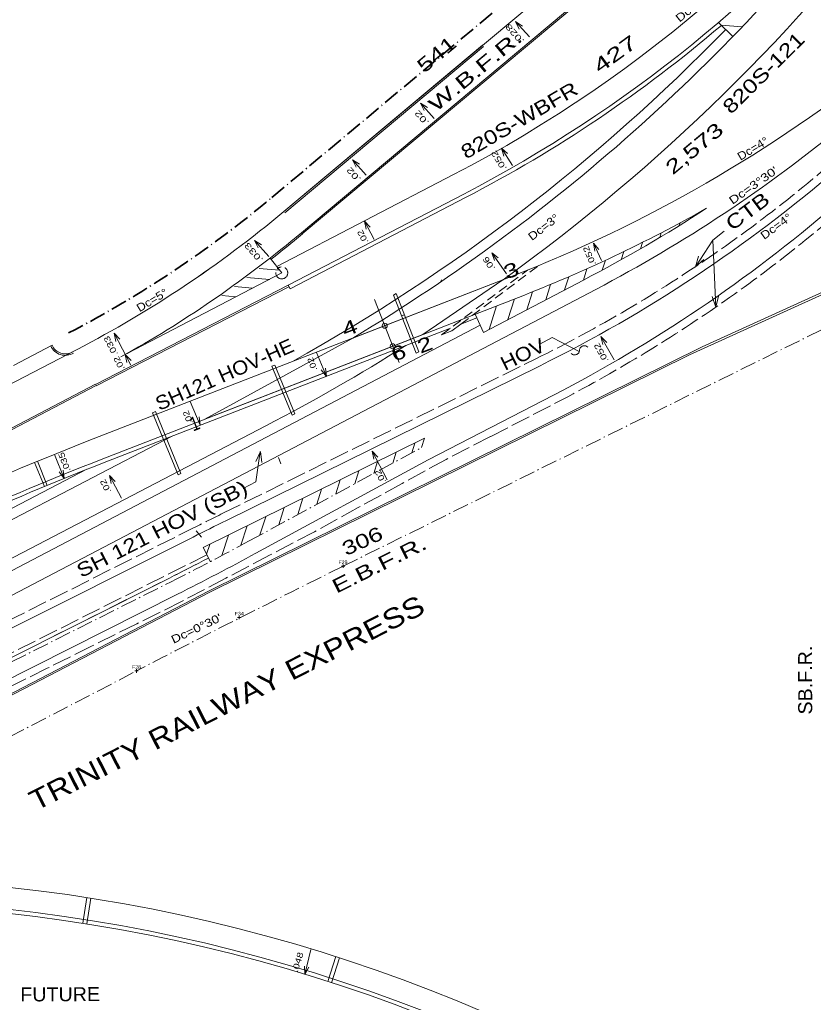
# Model space of a CAD drawing. Extents: x 2354993 to 2372084, y 6966390 to 6990057.
# Drawn here: x 2363431 to 2364225, y 6978118 to 6979100 of the extents above; entities that cross this region are included whole.
import ezdxf
from ezdxf.enums import TextEntityAlignment as Align

# ---------------------------------------------------------------- set-up
doc = ezdxf.new("R2010")
doc.units = 0
doc.header["$LTSCALE"] = 3.2
for name, pattern in [('DOT_DASHED', [7.7, 5, -1.2, 0.3, -1.2]), ('LONG_DASH_SHORT_DASH', [9.9, 6, -1.2, 1.5, -1.2]), ('LONG_DASHED', [7.5, 6, -1.5]), ('MEDIUM_DASHED', [4.5, 3, -1.5])]:
    doc.linetypes.add(name, pattern=pattern)
for name, color, linetype, lineweight in [('13', 7, 'Continuous', 13), ('17', 7, 'Continuous', 13), ('19', 7, 'Continuous', 13), ('23', 7, 'Continuous', 13), ('25', 7, 'Continuous', 13), ('28', 7, 'Continuous', 13), ('4', 7, 'Continuous', 13), ('5', 7, 'Continuous', 13), ('50', 7, 'LONG_DASH_SHORT_DASH', 13), ('6', 7, 'Continuous', 13), ('63', 7, 'Continuous', 13), ('9', 7, 'Continuous', 13)]:
    doc.layers.add(name, color=color, linetype=linetype, lineweight=lineweight)

msp = doc.modelspace()

# ---------------------------------------------------------------- linework, layer by layer
at = {"layer": '13'}
for p, q in [((2364124.311, 6978879.327), (2364135.635, 6978888.419)), ((2364124.311, 6978879.327), (2364107.051, 6978852.9)), ((2364124.311, 6978879.327), (2364127.473, 6978812.622)), ((2364107.051, 6978852.9), (2364110.158, 6978863.536)), ((2364107.051, 6978852.9), (2364115.294, 6978860.305)), ((2364127.472, 6978812.623), (2364123.858, 6978823.097)), ((2364127.473, 6978812.623), (2364129.916, 6978823.431)), ((2363667.59, 6978638.063), (2363671.897, 6978668.354)), ((2363672.046, 6978668.333), (2363667.62, 6978658.174)), ((2363672.047, 6978668.332), (2363673.633, 6978657.367)), ((2363667.59, 6978638.063), (2363654.762, 6978631.255))]:
    msp.add_line(p, q, dxfattribs=at)
for points in [[(2363950.859, 6978775.281), (2363963.619, 6978782.215), (2363990.892, 6978768.256)], [(2363999.577, 6978772.4), (2363998.454, 6978773.318), (2363997.504, 6978773.752), (2363996.636, 6978773.955), (2363995.824, 6978774), (2363995.058, 6978773.917), (2363994.332, 6978773.719), (2363993.644, 6978773.414), (2363992.997, 6978772.994), (2363992.396, 6978772.447), (2363991.85, 6978771.741), (2363991.388, 6978770.804), (2363991.214, 6978770.222), (2363991.098, 6978769.385), (2363990.979, 6978768.546), (2363990.806, 6978767.966), (2363990.674, 6978767.642), (2363990.343, 6978767.028), (2363990.06, 6978766.627), (2363989.798, 6978766.322), (2363989.197, 6978765.776), (2363988.55, 6978765.356), (2363987.863, 6978765.05), (2363987.137, 6978764.854), (2363986.37, 6978764.771), (2363985.559, 6978764.814), (2363984.69, 6978765.018), (2363984.046, 6978765.284), (2363983.739, 6978765.452), (2363983.238, 6978765.793), (2363982.618, 6978766.368)]]:
    msp.add_lwpolyline(points, dxfattribs=at)
at = {"layer": '17'}
for p, q in [((2363268.695, 6978481.439), (2363677.359, 6978693.821)), ((2363498.546, 6978222.377), (2363494.553, 6978196.824)), ((2363502.498, 6978221.759), (2363498.505, 6978196.207)), ((2363747.446, 6978163.351), (2363739.437, 6978138.405)), ((2363751.255, 6978162.128), (2363743.245, 6978137.182))]:
    msp.add_line(p, q, dxfattribs=at)
at = {"layer": '19'}
for p, q in [((2363927.094, 6979097.931), (2363930.771, 6979090.484)), ((2363927.094, 6979097.931), (2363934.149, 6979093.538)), ((2363941.005, 6979082.577), (2363927.094, 6979097.931)), ((2363832.045, 6979016.466), (2363835.722, 6979009.019)), ((2363832.045, 6979016.466), (2363839.1, 6979012.073)), ((2363845.956, 6979001.112), (2363832.045, 6979016.466)), ((2363913.032, 6978971.577), (2363915.358, 6978963.604)), ((2363913.032, 6978971.577), (2363919.215, 6978966.024)), ((2363924.06, 6978954.036), (2363913.032, 6978971.577)), ((2363763.983, 6978959.742), (2363767.66, 6978952.295)), ((2363763.983, 6978959.742), (2363771.038, 6978955.349)), ((2363777.894, 6978944.388), (2363763.983, 6978959.742)), ((2363776.001, 6978898.486), (2363777.835, 6978890.386)), ((2363776.001, 6978898.486), (2363781.833, 6978892.566)), ((2363785.936, 6978880.304), (2363776.001, 6978898.486)), ((2363666.116, 6978879.256), (2363669.793, 6978871.809)), ((2363666.116, 6978879.256), (2363673.171, 6978874.863)), ((2363680.616, 6978863.252), (2363666.116, 6978879.256)), ((2364005.199, 6978876.561), (2364006.371, 6978868.339)), ((2364005.199, 6978876.561), (2364010.533, 6978870.187)), ((2364012.986, 6978859.082), (2364005.199, 6978876.561)), ((2363903.322, 6978866.925), (2363909.75, 6978861.657)), ((2363525.767, 6978786.4), (2363527.497, 6978778.277)), ((2363525.767, 6978786.4), (2363531.523, 6978780.405)), ((2363542.615, 6978754.612), (2363525.767, 6978786.4)), ((2364012.378, 6978783.117), (2364014.392, 6978775.06)), ((2364012.378, 6978783.117), (2364018.341, 6978777.327)), ((2364025.8, 6978759.806), (2364012.378, 6978783.117)), ((2363532.44, 6978762.884), (2363539.021, 6978766.379)), ((2363536.944, 6978765.222), (2363538.674, 6978757.099)), ((2363536.944, 6978765.222), (2363542.7, 6978759.227)), ((2363728.247, 6978767.198), (2363738.051, 6978743.352)), ((2363738.051, 6978743.352), (2363732.905, 6978749.878)), ((2363738.051, 6978743.352), (2363737.118, 6978751.605)), ((2363601.957, 6978718.326), (2363611.761, 6978694.48)), ((2363611.761, 6978694.48), (2363610.828, 6978702.733)), ((2363466.118, 6978665.11), (2363475.922, 6978641.264)), ((2363783.747, 6978668.654), (2363785.477, 6978660.531)), ((2363783.747, 6978668.654), (2363789.503, 6978662.659)), ((2363798.92, 6978640.025), (2363783.747, 6978668.654)), ((2363475.922, 6978641.264), (2363470.776, 6978647.79)), ((2363475.922, 6978641.264), (2363474.989, 6978649.517)), ((2363521.224, 6978644.262), (2363522.954, 6978636.139)), ((2363521.224, 6978644.262), (2363526.98, 6978638.267)), ((2363533.298, 6978621.481), (2363521.224, 6978644.262)), ((2363613.023, 6978582.513), (2363607.877, 6978589.039)), ((2363716.338, 6978145.542), (2363716.086, 6978153.85))]:
    msp.add_line(p, q, dxfattribs=at)
for points in [[(2363918.021, 6978845.743), (2363903.322, 6978866.925), (2363906.006, 6978859.066)], [(2363722.648, 6978170.541), (2363716.338, 6978145.542), (2363720.499, 6978152.731)]]:
    msp.add_lwpolyline(points, dxfattribs=at)
at = {"layer": '23'}
msp.add_line((2363928.757, 6978804.834), (2363928.732, 6978804.883), dxfattribs=at)
at = {"layer": '25'}
for p, q in [((2363695.384, 6978907.983), (2364072.128, 6979223.133)), ((2363911.877, 6979053.229), (2364089.77, 6979202.039)), ((2363912.839, 6979052.078), (2364090.732, 6979200.888)), ((2364130.07, 6979096.947), (2364144.412, 6979083.009)), ((2363695.379, 6978907.981), (2363894.233, 6979074.323)), ((2363696.341, 6978906.829), (2363895.195, 6979073.173)), ((2363713.023, 6978886.887), (2363911.877, 6979053.229)), ((2363713.984, 6978885.737), (2363912.839, 6979052.079)), ((2363699.848, 6978834.335), (2363875.325, 6978925.541)), ((2363693.391, 6978846.757), (2363681.807, 6978861.611)), ((2363538.707, 6978766.357), (2363693.391, 6978846.757)), ((2363507.097, 6978735.295), (2363699.848, 6978834.335)), ((2363507.783, 6978733.961), (2363700.534, 6978833.001)), ((2363701.693, 6978830.785), (2363699.848, 6978834.335)), ((2363038.234, 6978322.559), (2364007.4, 6978830.292)), ((2363512.767, 6978660.249), (2363930.064, 6978822.286)), ((2363886.744, 6978805.465), (2363895.028, 6978787.227)), ((2358006.591, 6975920.846), (2363488.891, 6978770.331)), ((2363638.158, 6978599.34), (2363950.965, 6978753.691)), ((2363833.285, 6978672.206), (2363836.223, 6978681.461)), ((2362811.106, 6978184.667), (2363604.71, 6978582.7)), ((2363622.04, 6978558.072), (2363614.958, 6978572.167)), ((2363756.487, 6978553.588), (2363752.987, 6978553.588)), ((2363756.493, 6978553.591), (2363752.993, 6978553.591)), ((2363754.737, 6978555.338), (2363754.737, 6978551.838)), ((2363754.743, 6978555.341), (2363754.743, 6978551.841)), ((2363143.211, 6978301.576), (2363589.111, 6978525.607)), ((2363652.658, 6978502.288), (2363649.158, 6978502.288)), ((2363652.658, 6978502.288), (2363649.158, 6978502.288)), ((2363650.908, 6978504.038), (2363650.908, 6978500.538)), ((2363650.908, 6978504.038), (2363650.908, 6978500.538)), ((2363548.137, 6978450.65), (2363548.137, 6978447.15)), ((2363548.144, 6978450.653), (2363548.144, 6978447.153)), ((2363549.887, 6978448.9), (2363546.387, 6978448.9)), ((2363549.894, 6978448.903), (2363546.394, 6978448.903))]:
    msp.add_line(p, q, dxfattribs=at)
at = {"layer": '25', "linetype": 'LONG_DASHED'}
for p, q in [((2363634.618, 6978606.514), (2363947.425, 6978760.865)), ((2363902.287, 6978683.113), (2363968.888, 6978717.538)), ((2363902.235, 6978683.214), (2363857.739, 6978660.407)), ((2363857.675, 6978660.373), (2363813.85, 6978636.301)), ((2363813.786, 6978636.267), (2363769.961, 6978612.195)), ((2363769.897, 6978612.161), (2363726.072, 6978588.089)), ((2362775.435, 6978175.726), (2363601.123, 6978589.851)), ((2363726.072, 6978588.089), (2363681.803, 6978564.844)), ((2363618.55, 6978565.019), (2362905.562, 6978206.794)), ((2363681.803, 6978564.844), (2363637.534, 6978541.599)), ((2363135.13, 6978317.66), (2363581.03, 6978541.691)), ((2363637.533, 6978541.601), (2363593.264, 6978518.356)), ((2363593.265, 6978518.356), (2363548.487, 6978496.107)), ((2363548.488, 6978496.107), (2363503.71, 6978473.858)), ((2363503.711, 6978473.858), (2363458.933, 6978451.609)), ((2363458.934, 6978451.609), (2363414.156, 6978429.36))]:
    msp.add_line(p, q, dxfattribs=at)
at = {"layer": '25'}
msp.add_lwpolyline([(2363667.497, 6978566.51), (2363839.951, 6978659.895), (2363965.216, 6978724.645)], dxfattribs=at)
for centre, radius, start, end in [((2363247.127, 6980134.169), 1362.136, 297.46364, 320.4266), ((2362792.03, 6980397.363), 1885.859, 301.04574, 322.89258), ((2363323.326, 6980025.663), 1418.395, 296.26348, 310.78211), ((2363406.512, 6980170.6), 1446.395, 291.22127, 299.46693), ((2363298.192, 6980015.937), 1453.395, 297.31887, 310.6767), ((2362961.103, 6979785.775), 1144.416, 297.46365, 309.91281), ((2362961.101, 6979785.775), 1171.963, 299.53559, 309.91255), ((2362961.101, 6979785.775), 1173.462, 307.94874, 309.91255), ((2364544.669, 6976002.774), 2850.789, 111.22127, 117.46089), ((2366179.689, 6973448.679), 5743.578, 116.26348, 116.63614), ((2362296.691, 6981097.975), 2878.789, 296.67607, 298.43586)]:
    msp.add_arc(centre, radius, start, end, dxfattribs=at)
at = {"layer": '25', "linetype": 'LONG_DASHED'}
for centre, radius, start, end in [((2363323.326, 6980025.663), 1410.395, 296.26348, 313.14638), ((2363298.192, 6980015.937), 1461.395, 297.31887, 312.20163), ((2366179.689, 6973448.679), 5751.578, 116.26348, 116.63614), ((2362296.691, 6981097.975), 2860.789, 296.67607, 297.55731)]:
    msp.add_arc(centre, radius, start, end, dxfattribs=at)
at = {"layer": '28'}
msp.add_line((2363692.6, 6978656.074), (2363690.033, 6978662.131), dxfattribs=at)
at = {"layer": '4'}
for p, q in [((2364132.776, 6979094.317), (2364153.623, 6979092.553)), ((2363688.388, 6978853.171), (2363865.179, 6978945.061)), ((2363701.693, 6978830.785), (2363877.17, 6978921.991)), ((2363658.618, 6978842.121), (2363681.022, 6978840.327)), ((2363670.716, 6978851.185), (2363691.218, 6978849.543)), ((2363646.219, 6978833.081), (2363664.295, 6978831.633)), ((2363633.508, 6978824.067), (2363647.572, 6978822.941))]:
    msp.add_line(p, q, dxfattribs=at)
for centre, radius, start, end in [((2363247.127, 6980134.169), 1340.136, 297.46364, 325.00264), ((2362792.03, 6980397.361), 1919.859, 305.78394, 323.02193), ((2362792.03, 6980397.363), 1875.859, 299.08835, 315.81698), ((2363247.127, 6980134.169), 1366.136, 297.46364, 310.42224), ((2362792.03, 6980397.361), 1919.859, 297.46086, 302.28095)]:
    msp.add_arc(centre, radius, start, end, dxfattribs=at)
at = {"layer": '5'}
for p, q in [((2364091.724, 6978896.81), (2364090.85, 6978894.042)), ((2364072.843, 6978886.833), (2364071.375, 6978882.184)), ((2364054.093, 6978877.273), (2364052.06, 6978870.836)), ((2364035.469, 6978868.114), (2364032.897, 6978859.975)), ((2364016.964, 6978859.339), (2364013.878, 6978849.575)), ((2363504.803, 6978680.758), (2363922.1, 6978842.795)), ((2363980.304, 6978842.888), (2363976.143, 6978829.722)), ((2363998.577, 6978850.935), (2363994.993, 6978839.597)), ((2363852.973, 6978839.977), (2363852.165, 6978837.688)), ((2363895.028, 6978787.227), (2363994.993, 6978839.597)), ((2363962.138, 6978835.184), (2363957.29, 6978819.845)), ((2363255.18, 6978436.214), (2364007.4, 6978830.292)), ((2363944.076, 6978827.812), (2363938.437, 6978809.968)), ((2364101.183, 6978764.916), (2364238.257, 6978827.035)), ((2364113.723, 6978772.795), (2364238.524, 6978829.352)), ((2363908.183, 6978813.789), (2363900.732, 6978790.215)), ((2363926.115, 6978820.752), (2363919.585, 6978800.092)), ((2363244.971, 6978455.701), (2363891.715, 6978794.521)), ((2363872.294, 6978795.563), (2363888.401, 6978801.817)), ((2363514.215, 6978656.52), (2363861.967, 6978791.553)), ((2363425.177, 6978754.243), (2363463.775, 6978774.478)), ((2363482.757, 6978767.142), (2363488.89, 6978770.33)), ((2363620.009, 6978528.496), (2364113.723, 6978772.795)), ((2363620.695, 6978527.162), (2364101.183, 6978764.916)), ((2362654.988, 6978292.473), (2363507.292, 6978735.395)), ((2362655.626, 6978291.114), (2363508.018, 6978734.082)), ((2362391.142, 6978063.692), (2363583.984, 6978683.611)), ((2363614.958, 6978572.167), (2363836.223, 6978681.461)), ((2363826.447, 6978676.637), (2363823.35, 6978666.838)), ((2363807.809, 6978667.441), (2363804.378, 6978656.588)), ((2363789.173, 6978658.245), (2363785.408, 6978646.338)), ((2363248.405, 6978520.48), (2363498.513, 6978650.46)), ((2363770.533, 6978649.048), (2363766.437, 6978636.089)), ((2363751.895, 6978639.85), (2363747.465, 6978625.838)), ((2363733.259, 6978630.655), (2363728.496, 6978615.589)), ((2363714.618, 6978621.457), (2363709.525, 6978605.339)), ((2363695.982, 6978612.261), (2363690.554, 6978595.09)), ((2363677.345, 6978603.064), (2363671.584, 6978584.84)), ((2363658.704, 6978593.866), (2363652.612, 6978574.59)), ((2363640.067, 6978584.67), (2363633.642, 6978564.34)), ((2363621.409, 6978575.408), (2363618.289, 6978565.537)), ((2363135.13, 6978317.66), (2363581.03, 6978541.691)), ((2363620.009, 6978528.496), (2363045.424, 6978230.005)), ((2363620.695, 6978527.162), (2363049.66, 6978230.516))]:
    msp.add_line(p, q, dxfattribs=at)
for centre, radius, start, end in [((2363406.512, 6980170.6), 1424.395, 291.22127, 308.69896), ((2363336.186, 6980111.513), 1446.395, 297.64942, 309.4527), ((2363333.422, 6980115.951), 1437.622, 297.39902, 303.07689), ((2362961.102, 6979785.775), 1144.416, 297.46365, 309.91255), ((2363476.995, 6978780.281), 15.938, 203.70124, 301.18072), ((2363476.995, 6978780.281), 14.438, 203.70124, 301.18072), ((2364544.669, 6976002.774), 2872.789, 111.22127, 117.46089), ((2364544.669, 6976002.774), 2846.789, 111.22127, 117.46089), ((2362296.691, 6981097.975), 2860.789, 296.67607, 297.55731), ((2362823.255, 6979494.499), 2021.91, 312.68984, 326.1095), ((2363244.672, 6976597.082), 1645.014, 38.12295, 103.3303), ((2363244.672, 6976597.082), 1623.014, 38.12295, 103.3303), ((2363244.672, 6976597.082), 1619.014, 38.12295, 103.3303)]:
    msp.add_arc(centre, radius, start, end, dxfattribs=at)
at = {"layer": '50'}
msp.add_circle((2363693.391, 6978846.757), 6, dxfattribs=at)
at = {"layer": '6', "linetype": 'DOT_DASHED', "lineweight": 35}
msp.add_line((2363683.514, 6978922.173), (2364060.258, 6979237.323), dxfattribs=at)
at = {"layer": '6', "linetype": 'DOT_DASHED'}
for p, q in [((2363754.737, 6978553.588), (2364601.335, 6978971.879)), ((2363754.737, 6978553.588), (2364596.754, 6978969.616)), ((2363660.831, 6978578.821), (2363833.285, 6978672.206)), ((2363136.926, 6978314.086), (2363582.826, 6978538.117)), ((2360272.717, 6976747.357), (2363548.144, 6978448.903)), ((2360272.718, 6976747.358), (2363548.137, 6978448.9)), ((2360272.718, 6976747.358), (2363548.137, 6978448.9))]:
    msp.add_line(p, q, dxfattribs=at)
at = {"layer": '6', "linetype": 'MEDIUM_DASHED'}
for p, q in [((2363872.294, 6978795.563), (2363949.948, 6978853.947)), ((2363853.114, 6978784.897), (2363939.034, 6978849.495))]:
    msp.add_line(p, q, dxfattribs=at)
at = {"layer": '6'}
for p, q in [((2363805.233, 6978824.449), (2363807.803, 6978826.119)), ((2363827.758, 6978766.441), (2363805.233, 6978824.449)), ((2363830.432, 6978767.843), (2363807.803, 6978826.119)), ((2363816.066, 6978804.84), (2363813.269, 6978803.754)), ((2363863.441, 6978788.907), (2363872.294, 6978795.563)), ((2363853.114, 6978784.897), (2363863.441, 6978788.907)), ((2363827.758, 6978766.441), (2363830.432, 6978767.843)), ((2363683.58, 6978753.396), (2363686.378, 6978754.482)), ((2363686.378, 6978754.482), (2363706.492, 6978705.869)), ((2363683.58, 6978753.396), (2363703.838, 6978704.436)), ((2363564.232, 6978707.053), (2363567.029, 6978708.139)), ((2363564.232, 6978707.053), (2363589.91, 6978644.993)), ((2363703.838, 6978704.436), (2363706.492, 6978705.869)), ((2363446.294, 6978657.296), (2363456.235, 6978633.272)), ((2363449.067, 6978658.442), (2363459.008, 6978634.417))]:
    msp.add_line(p, q, dxfattribs=at)
msp.add_lwpolyline([(2363567.029, 6978708.139), (2363592.582, 6978646.382), (2363589.91, 6978644.993)], dxfattribs=at)
at = {"layer": '6', "linetype": 'DOT_DASHED', "lineweight": 35}
msp.add_arc((2362961.103, 6979785.775), 1125.916, 297.46365, 309.91281, dxfattribs=at)
at = {"layer": '6', "linetype": 'DOT_DASHED'}
for centre, radius, start, end in [((2362296.691, 6981097.975), 2864.789, 296.67607, 298.43586), ((2368830.754, 6968280.015), 11459.156, 116.29328, 117.45135)]:
    msp.add_arc(centre, radius, start, end, dxfattribs=at)
at = {"layer": '63'}
for p, q in [((2363810.651, 6978757.145), (2363786.194, 6978820.13)), ((2363764.611, 6978781.642), (2363616.642, 6978700.584))]:
    msp.add_line(p, q, dxfattribs=at)
msp.add_lwpolyline([(2363616.642, 6978700.584), (2363834.48, 6978785.171), (2363914.559, 6978839.867), (2363764.611, 6978781.642)], dxfattribs=at)
for centre in [(2363796.353, 6978793.967), (2363804.317, 6978773.458)]:
    msp.add_circle(centre, 2.5, dxfattribs=at)
at = {"layer": '9'}
msp.add_arc((2360722.521, 6984327.136), 5729.573, 359.50797, 359.50797, dxfattribs=at)

# ---------------------------------------------------------------- texts
at = {"layer": '13'}
for s, height, rotation, width, p in [('541', 14, 39.872, 1.4, (2363835.916, 6979045.85)), ('W.B.F.R.', 14, 39.604, 1.5, (2363847.432, 6979006.886)), ('427', 14, 35.998, 1.55, (2364011.217, 6979045.622)), ('820S-121', 14, 44.651, 1.3, (2364142.504, 6979004.629)), ('820S-WBFR', 14, 30.36, 1.25, (2363877.779, 6978960.054)), ('2,573', 14, 39.872, 1.45, (2364084.325, 6978944.101)), ('CTB', 14, 36.829, 1.3, (2364143.802, 6978888.203)), ('SH121 HOV-HE', 14, 23.865, 1.1, (2363570.985, 6978708.718)), ('HOV', 14, 26.59, 1.15, (2363916.601, 6978748.75)), ('SH 121 HOV (SB)', 14, 27.086, 1.25, (2363492.872, 6978541.606)), ('306', 14, 24.683, 1.35, (2363757.765, 6978563.639)), ('E.B.F.R.', 14, 26.495, 1.45, (2363748.056, 6978525.975)), ('TRINITY RAILWAY EXPRESS', 20, 26.985, 1.2, (2363447.53, 6978308.55)), ('SB.F.R.', 14, 90.062, 1.05, (2364223.754, 6978405.383))]:
    msp.add_text(s, height=height, rotation=rotation, dxfattribs=dict(at, width=width)).set_placement(p)
at = {"layer": '13', "width": 1.05}
msp.add_text('FUTURE', height=14, rotation=0.302, dxfattribs=at).set_placement((2363471.904, 6978118.726), align=Align.CENTER)
at = {"layer": '17'}
for s, rotation, width, p in [("Dc=4°15'", 39.192, 1.25, (2364091.184, 6979096.857)), ('Dc=4°', 31.442, 1.15, (2364152.009, 6978958.787)), ("Dc=3°30'", 35.132, 1.3, (2364144.051, 6978914.755)), ('Dc=3°', 37.449, 1.2, (2363943.524, 6978878.531)), ('Dc=4°', 36.1, 1.2, (2364175.714, 6978879.656)), ('Dc=5°', 30.975, 1.15, (2363551.245, 6978807.403)), ("Dc=0°30'", 25.548, 1.25, (2363585.22, 6978476.002))]:
    msp.add_text(s, height=8, rotation=rotation, dxfattribs=dict(at, width=width)).set_placement(p)
at = {"layer": '19'}
for s, height, rotation, width, p in [('.028', 6, 131.299, 1.5, (2363936.266, 6979078.866)), ('.02', 6, 131.299, 1.5, (2363841.217, 6978997.401)), ('.052', 6, 121.279, 1.4, (2363918.746, 6978951.207)), ('.02', 6, 131.299, 1.5, (2363773.155, 6978940.677)), ('.02', 6, 117.775, 1.3, (2363780.46, 6978877.805)), ('.033', 6, 131.299, 1.5, (2363675.288, 6978860.191)), ('.052', 6, 113.136, 1.3, (2364007.796, 6978855.545)), ('.06', 6, 123.88, 1.35, (2363907.187, 6978851.421)), ('.033', 6, 117.046, 1.35, (2363529.963, 6978765.664)), ('.052', 6, 119.055, 1.35, (2364020.576, 6978759.048)), ('.02', 6, 117.046, 1.3, (2363536.734, 6978751.229)), ('.02', 5.999, 110.961, 1.25, (2363729.22, 6978750.076)), ('.02', 5.999, 110.961, 1.25, (2363604.815, 6978696.885)), ('.035', 5.999, 110.961, 1.3, (2363482.514, 6978649.258)), ('.02', 6, 117.046, 1.3, (2363797.954, 6978638.161)), ('.02', 6, 117.046, 1.3, (2363523.217, 6978628.408)), ('.048', 5.999, 72.722, 1.3, (2363709.268, 6978147.314))]:
    msp.add_text(s, height=height, rotation=rotation, dxfattribs=dict(at, width=width)).set_placement(p)
at = {"layer": '25'}
for s, width, p in [('F29', 1.1, (2363750.237, 6978555.791)), ('F34', 1.15, (2363646.237, 6978504.488)), ('F28', 1.15, (2363543.556, 6978451.103))]:
    msp.add_text(s, height=3.5, dxfattribs=dict(at, width=width)).set_placement(p)
at = {"layer": '63'}
for s, width, p in [('3', 1.4, (2363925.321, 6978842.701)), ('4', 1.45, (2363763.753, 6978785.27)), ('6', 1.35, (2363812.686, 6978760.473)), ('2', 1.4, (2363838.948, 6978768.499)), ('1', 0.85, (2363608.79, 6978689.722))]:
    msp.add_text(s, height=14, rotation=21.221, dxfattribs=dict(at, width=width)).set_placement(p, align=Align.CENTER)

doc.saveas('drawing.dxf')
